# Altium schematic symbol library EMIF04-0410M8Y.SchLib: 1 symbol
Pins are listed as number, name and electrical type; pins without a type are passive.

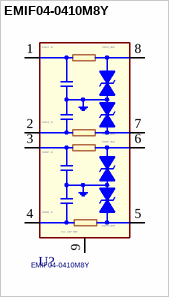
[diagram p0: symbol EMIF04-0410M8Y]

## EMIF04-0410M8Y
designator U?
footprint ST_QFN50P200x150x75-8L
pins: 1 ISOLP_IC, 2 ISOLM_IC, 3 ISOHP_IC, 4 ISOHM_IC, 5 ISOHM_BUS, 6 ISOHP_BUS, 7 ISOLM_BUS, 8 ISOLP_BUS, 9 GND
